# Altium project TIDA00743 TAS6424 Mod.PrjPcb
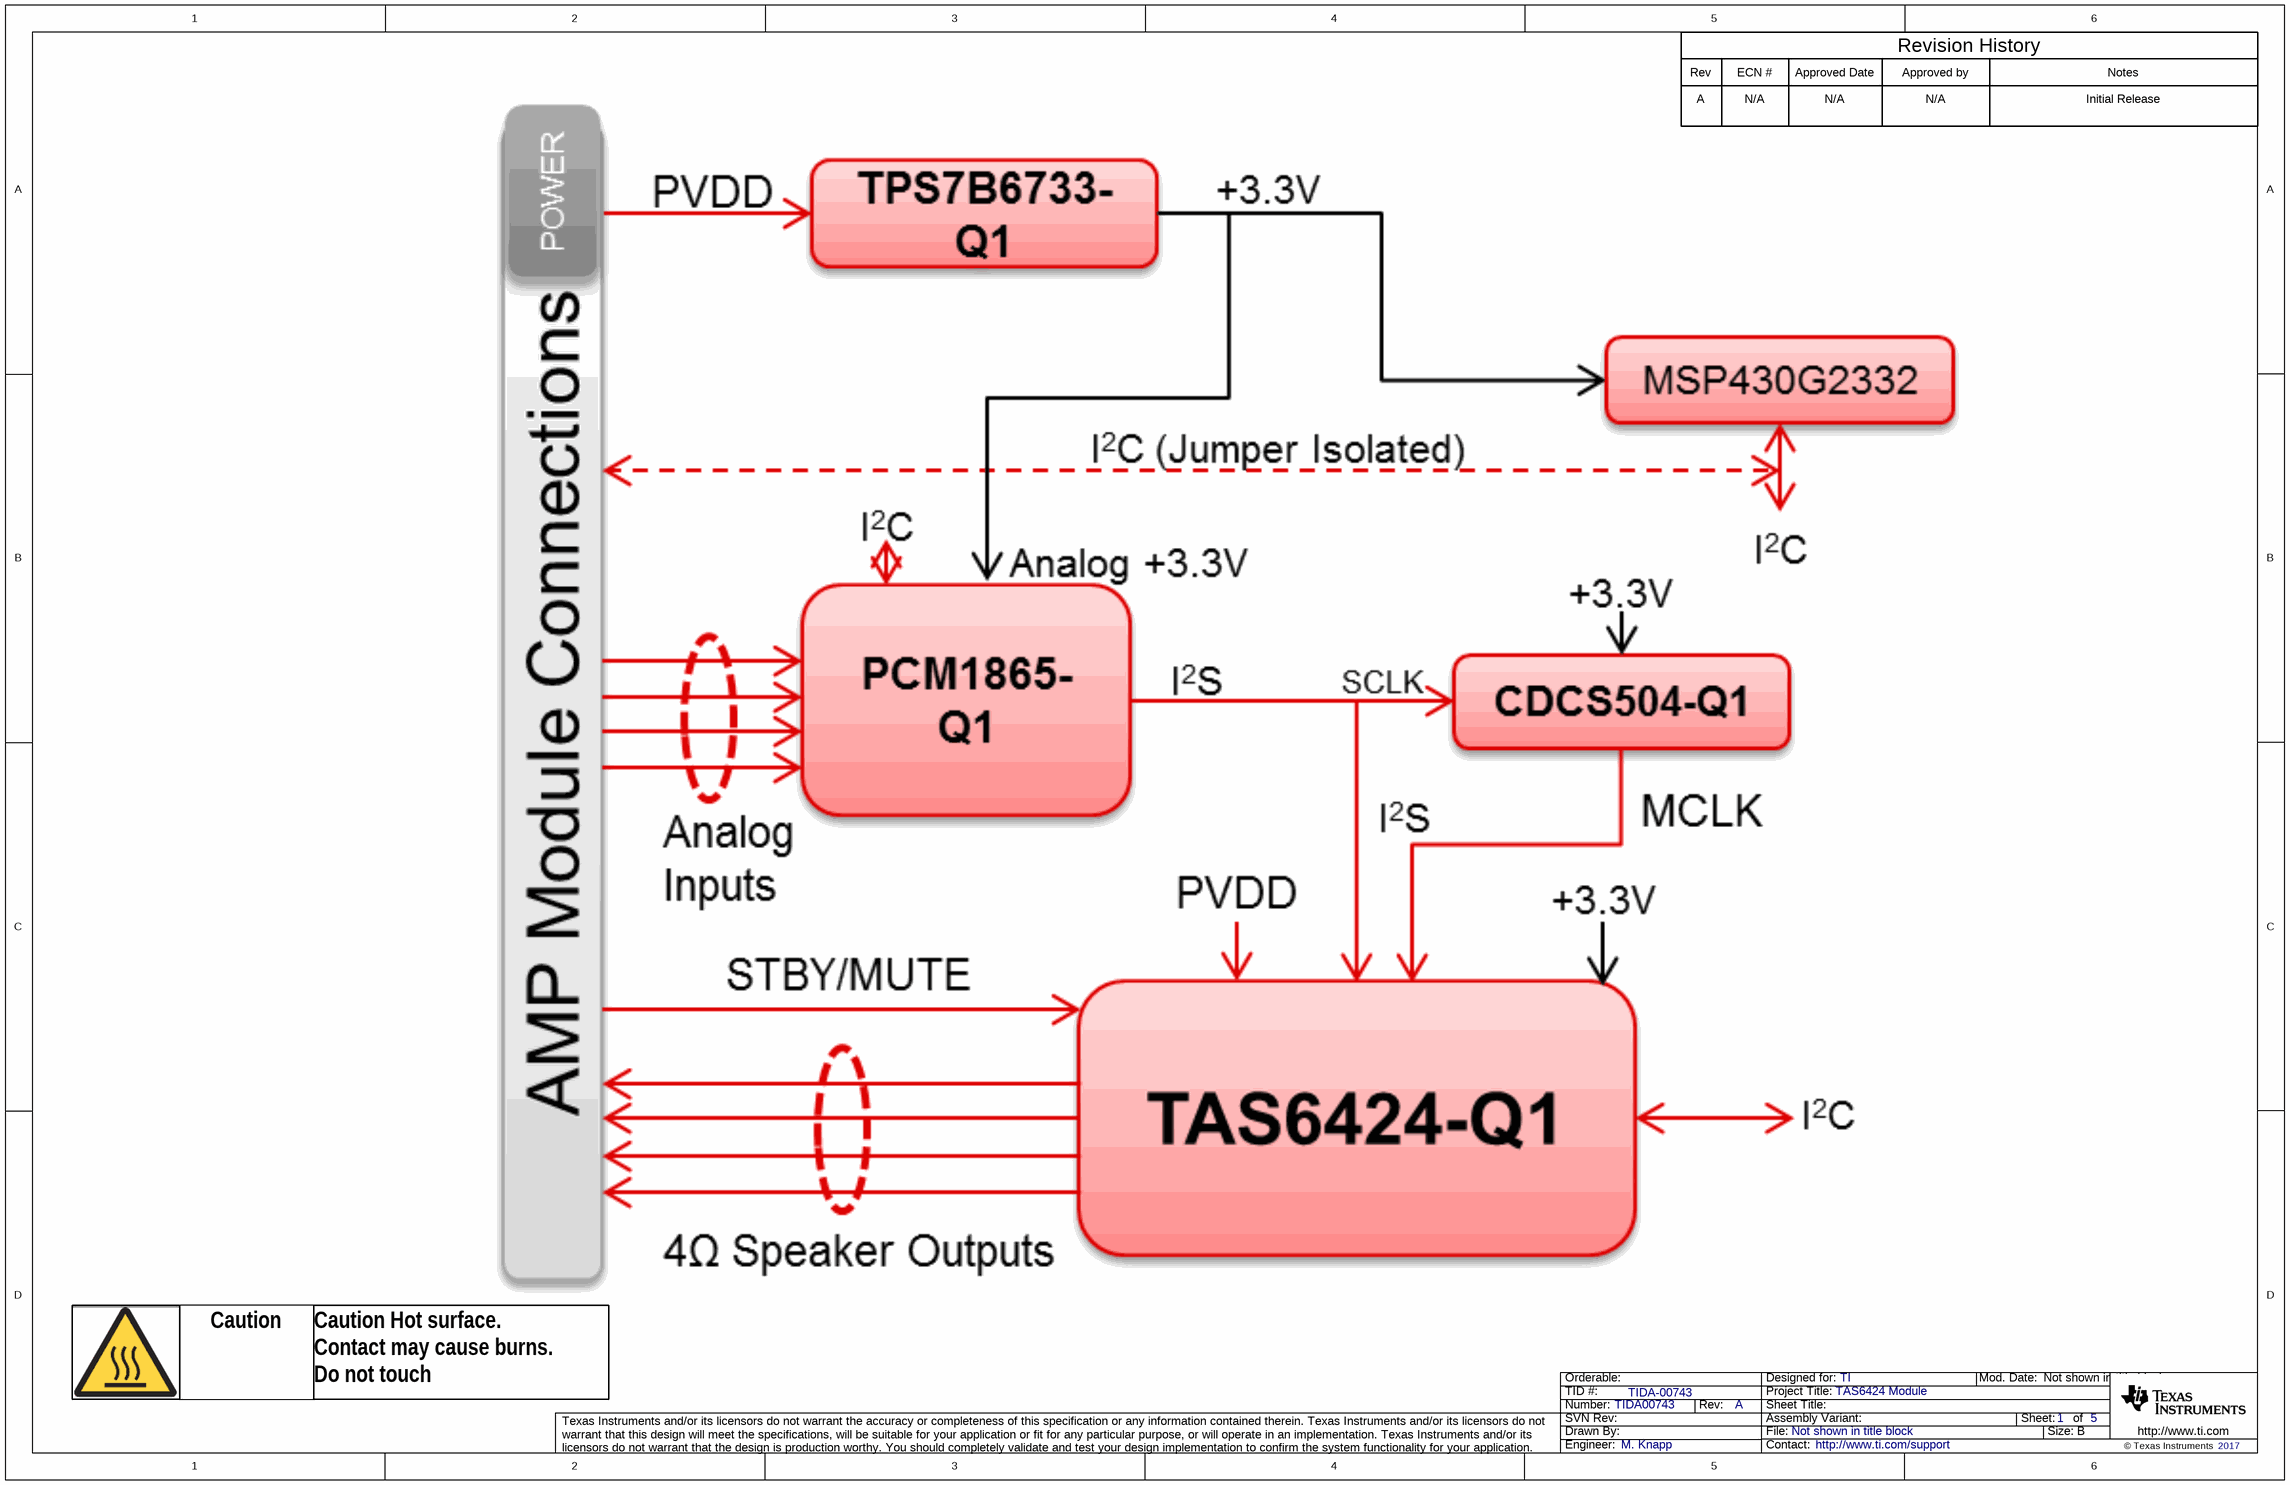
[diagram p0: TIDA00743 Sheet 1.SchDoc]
TID: TIDA-00743; TechSupport: http://www.ti.com/support; SCH_Rev: A; PRJ_Title: TAS6424 Module; PRJ_Number: TIDA00743; PRJ_Engineer: M. Knapp; PRJ_Customer: TI; PCB_Rev: A; PCB_Layout: M. Knapp; CopyrightYear: 2017
5 sheets, 145 parts. Net scope: global (net labels, ports and power ports of the same name join across sheets).
Board file: TIDA00743 PCB.PcbDoc
Sheets:
  TIDA00743 Sheet 1.SchDoc
  TIDA00743 Sheet 2.SchDoc
  TIDA00743 Sheet 3.SchDoc
  TIDA00743 Sheet 4.SchDoc
  TIDA00743 Sheet 5.SchDoc

## Sheet TIDA00743 Sheet 1.SchDoc
size 431 x 279 mm; Date: Not shown in title block; ApprovedBy: Not shown in title block; CheckedBy: Not shown in title block; Author: Not shown in title block; CompanyName: Not shown in title block; Engineer: Not shown in title block; Organization: Not shown in title block; Address1: Not shown in title block; Address2: Not shown in title block; Address3: Not shown in title block; Address4: Not shown in title block; DocumentNumber: 1; Revision: Use project parameter SCH_Rev; SheetNumber: 1; SheetTotal: 5; PageSetup: Record=PageOptions¦CenterHorizontal=True¦CenterVertical=True¦PrintScale=1.00¦XCorrection=1.00¦YCorrection=1.00¦PrintKind=0¦BorderSize=5000000¦LeftOffset=0¦BottomOffset=0¦Orientation=2¦PaperLength=1000¦PaperWidth=1000¦Scale=100¦PaperSource=15¦PrintQuality=600¦MediaType=1¦DitherType=10¦PaperKind=Letter¦PrintScaleMode=1

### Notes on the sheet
- Rev
- A
- ECN #
- N/A
- Approved Date
- Approved by
- Revision History
- Notes
- Initial Release
- Caution
- Caution Hot surface.
  Contact may cause burns.
  Do not touch

## Sheet TIDA00743 Sheet 2.SchDoc
size 431 x 279 mm; Date: Not shown in title block; ApprovedBy: Not shown in title block; CheckedBy: Not shown in title block; Author: Not shown in title block; CompanyName: Not shown in title block; Engineer: Not shown in title block; Organization: Not shown in title block; Address1: Not shown in title block; Address2: Not shown in title block; Address3: Not shown in title block; Address4: Not shown in title block; DocumentNumber: 2; Revision: Use project parameter SCH_Rev; SheetNumber: 2; SheetTotal: 5; PageSetup: Record=PageOptions¦CenterHorizontal=True¦CenterVertical=True¦PrintScale=1.00¦XCorrection=1.00¦YCorrection=1.00¦PrintKind=0¦BorderSize=5000000¦LeftOffset=0¦BottomOffset=0¦Orientation=2¦PaperLength=1000¦PaperWidth=1000¦Scale=100¦PaperSource=15¦PrintQuality=600¦MediaType=1¦DitherType=10¦PaperKind=Letter¦PrintScaleMode=1
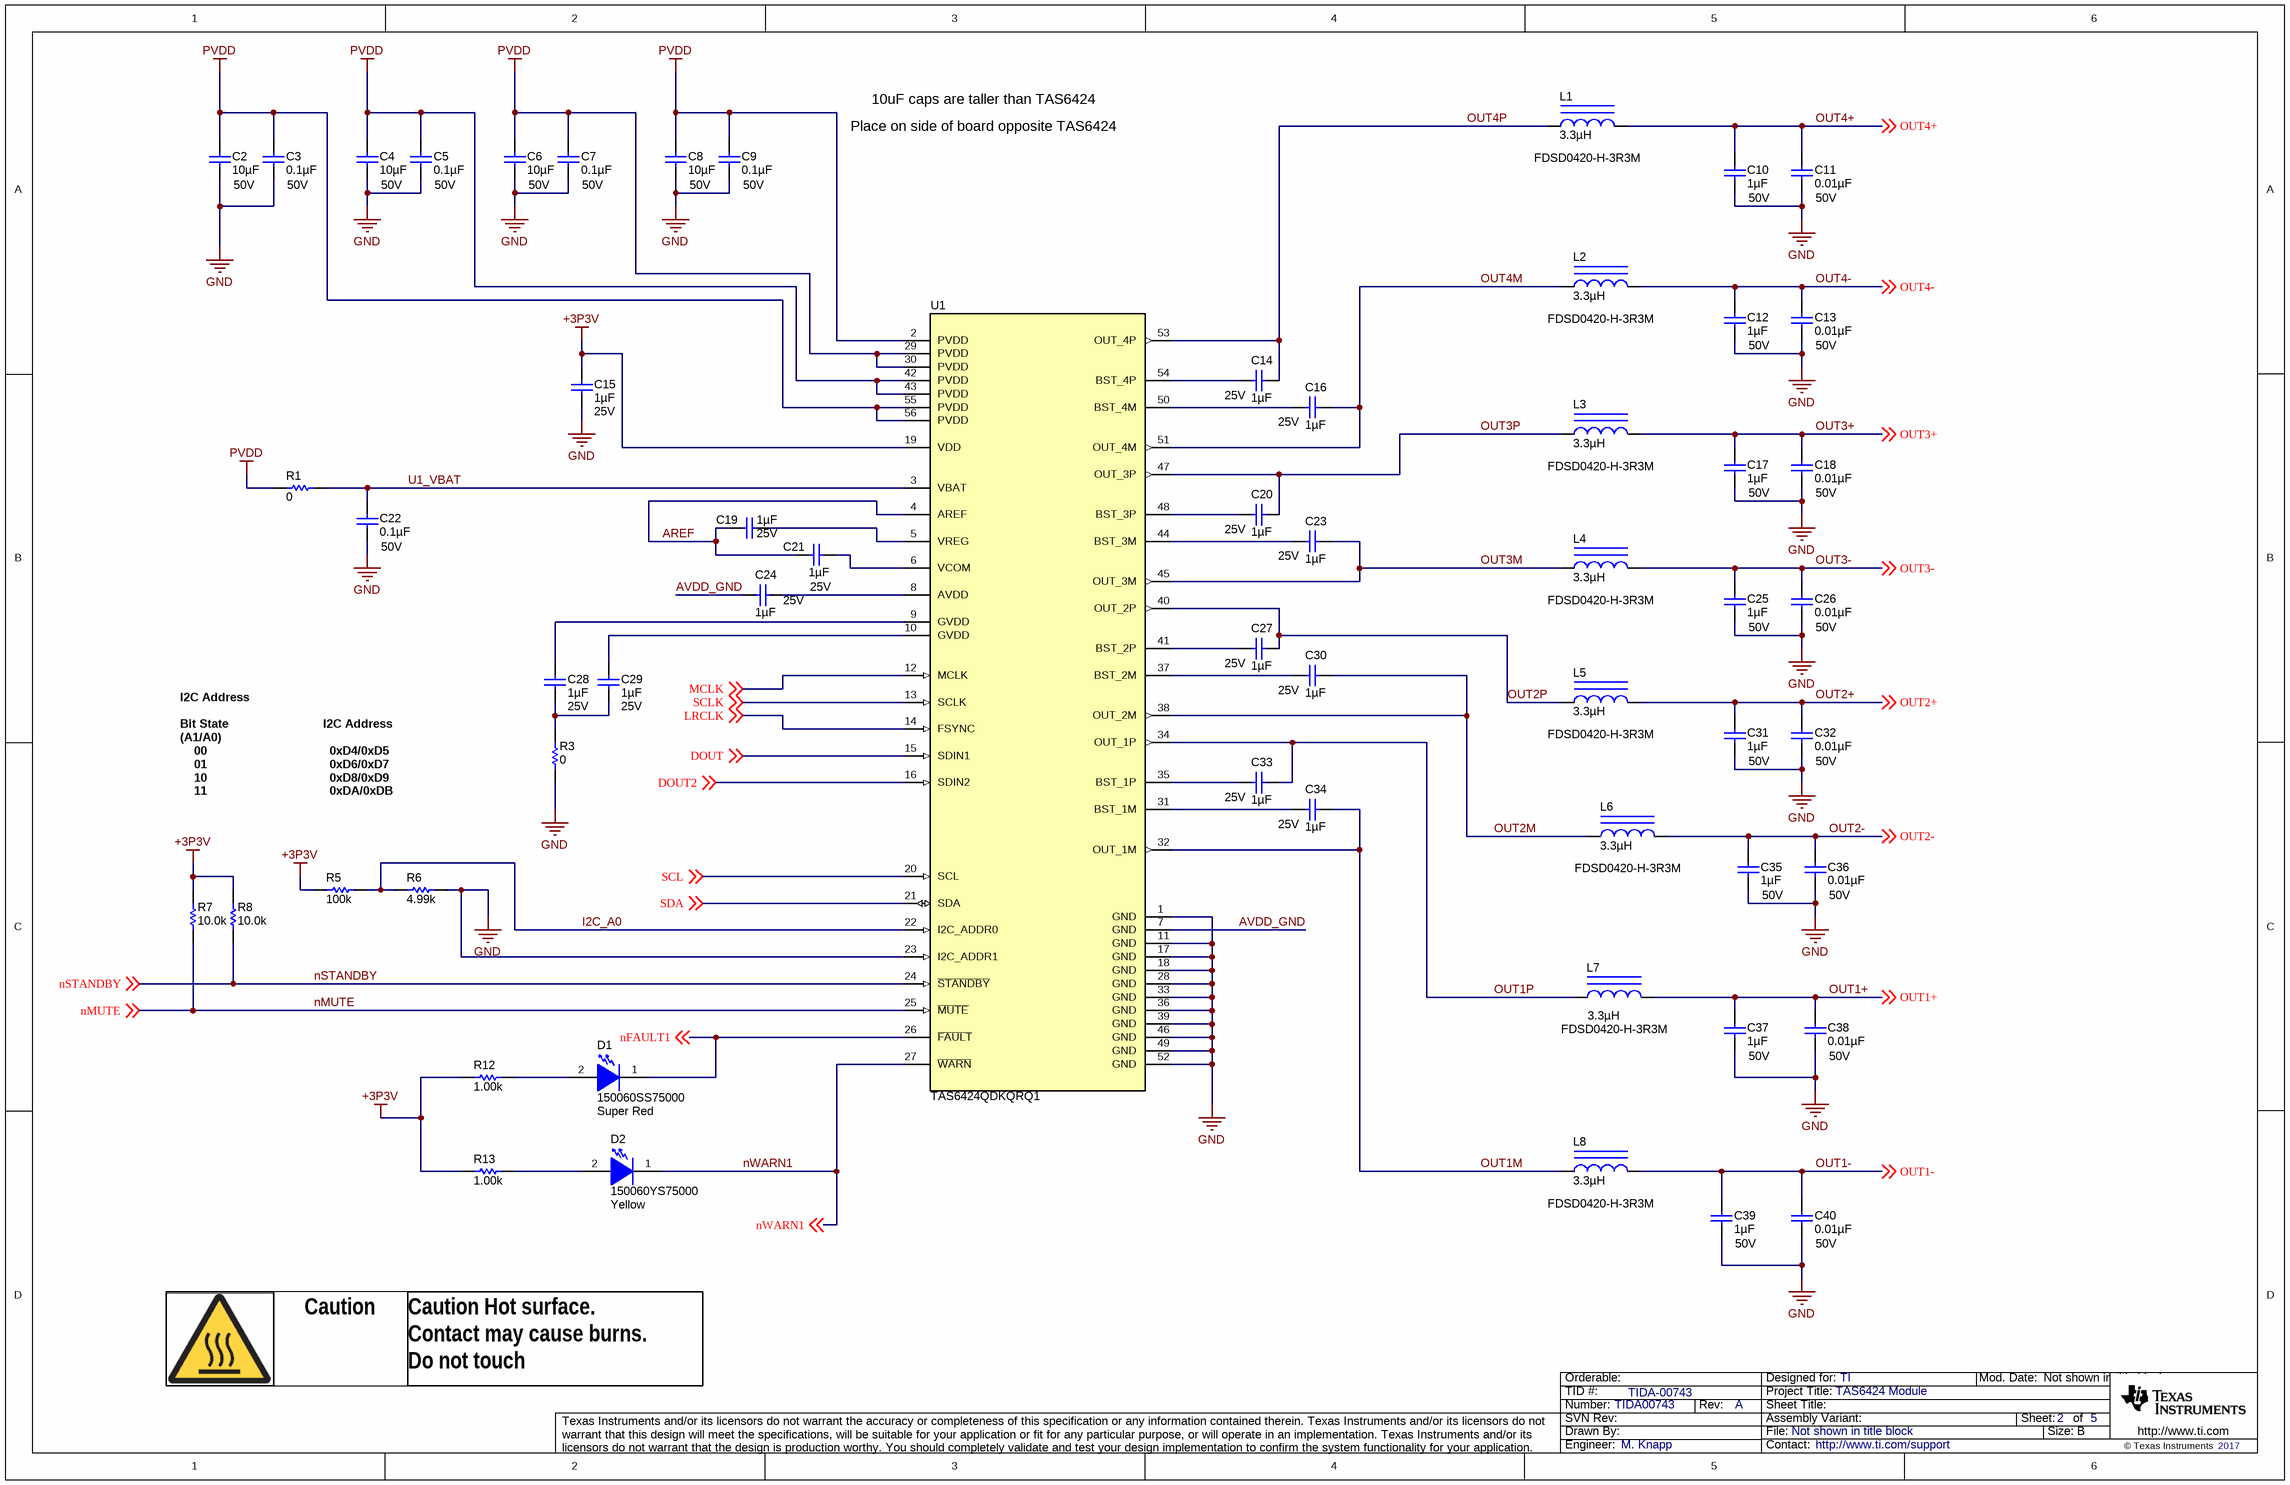
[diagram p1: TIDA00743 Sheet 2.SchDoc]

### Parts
C2  ValueDisplayed: 10µF  Value2: 50V  [1210L]  (hidden comment: GRM32ER71H106KA12L)
C3  ValueDisplayed: 0.1µF  Value2: 50V  [0402L]  (hidden comment: C1005X7R1H104K050BB)
C4  ValueDisplayed: 10µF  Value2: 50V  [1210L]  (hidden comment: GRM32ER71H106KA12L)
C5  ValueDisplayed: 0.1µF  Value2: 50V  [0402L]  (hidden comment: C1005X7R1H104K050BB)
C6  ValueDisplayed: 10µF  Value2: 50V  [1210L]  (hidden comment: GRM32ER71H106KA12L)
C7  ValueDisplayed: 0.1µF  Value2: 50V  [0402L]  (hidden comment: C1005X7R1H104K050BB)
C8  ValueDisplayed: 10µF  Value2: 50V  [1210L]  (hidden comment: GRM32ER71H106KA12L)
C9  ValueDisplayed: 0.1µF  Value2: 50V  [0402L]  (hidden comment: C1005X7R1H104K050BB)
C10  ValueDisplayed: 1µF  Value2: 50V  [0805L]  (hidden comment: GRM21BR71H105KA12L)
C11  ValueDisplayed: 0.01µF  Value2: 50V  [0402L]  (hidden comment: GCM155R71H103KA55D)
C12  ValueDisplayed: 1µF  Value2: 50V  [0805L]  (hidden comment: GRM21BR71H105KA12L)
C13  ValueDisplayed: 0.01µF  Value2: 50V  [0402L]  (hidden comment: GCM155R71H103KA55D)
C14  ValueDisplayed: 1µF  Value2: 25V  [0603L]  (hidden comment: C1608X7R1E105K080AB)
C15  ValueDisplayed: 1µF  Value2: 25V  [0603L]  (hidden comment: C1608X7R1E105K080AB)
C16  ValueDisplayed: 1µF  Value2: 25V  [0603L]  (hidden comment: C1608X7R1E105K080AB)
C17  ValueDisplayed: 1µF  Value2: 50V  [0805L]  (hidden comment: GRM21BR71H105KA12L)
C18  ValueDisplayed: 0.01µF  Value2: 50V  [0402L]  (hidden comment: GCM155R71H103KA55D)
C19  ValueDisplayed: 1µF  Value2: 25V  [0603L]  (hidden comment: C1608X7R1E105K080AB)
C20  ValueDisplayed: 1µF  Value2: 25V  [0603L]  (hidden comment: C1608X7R1E105K080AB)
C21  ValueDisplayed: 1µF  Value2: 25V  [0603L]  (hidden comment: C1608X7R1E105K080AB)
C22  ValueDisplayed: 0.1µF  Value2: 50V  [0402L]  (hidden comment: C1005X7R1H104K050BB)
C23  ValueDisplayed: 1µF  Value2: 25V  [0603L]  (hidden comment: C1608X7R1E105K080AB)
C24  ValueDisplayed: 1µF  Value2: 25V  [0603L]  (hidden comment: C1608X7R1E105K080AB)
C25  ValueDisplayed: 1µF  Value2: 50V  [0805L]  (hidden comment: GRM21BR71H105KA12L)
C26  ValueDisplayed: 0.01µF  Value2: 50V  [0402L]  (hidden comment: GCM155R71H103KA55D)
C27  ValueDisplayed: 1µF  Value2: 25V  [0603L]  (hidden comment: C1608X7R1E105K080AB)
C28  ValueDisplayed: 1µF  Value2: 25V  [0603L]  (hidden comment: C1608X7R1E105K080AB)
C29  ValueDisplayed: 1µF  Value2: 25V  [0603L]  (hidden comment: C1608X7R1E105K080AB)
C30  ValueDisplayed: 1µF  Value2: 25V  [0603L]  (hidden comment: C1608X7R1E105K080AB)
C31  ValueDisplayed: 1µF  Value2: 50V  [0805L]  (hidden comment: GRM21BR71H105KA12L)
C32  ValueDisplayed: 0.01µF  Value2: 50V  [0402L]  (hidden comment: GCM155R71H103KA55D)
C33  ValueDisplayed: 1µF  Value2: 25V  [0603L]  (hidden comment: C1608X7R1E105K080AB)
C34  ValueDisplayed: 1µF  Value2: 25V  [0603L]  (hidden comment: C1608X7R1E105K080AB)
C35  ValueDisplayed: 1µF  Value2: 50V  [0805L]  (hidden comment: GRM21BR71H105KA12L)
C36  ValueDisplayed: 0.01µF  Value2: 50V  [0402L]  (hidden comment: GCM155R71H103KA55D)
C37  ValueDisplayed: 1µF  Value2: 50V  [0805L]  (hidden comment: GRM21BR71H105KA12L)
C38  ValueDisplayed: 0.01µF  Value2: 50V  [0402L]  (hidden comment: GCM155R71H103KA55D)
C39  ValueDisplayed: 1µF  Value2: 50V  [0805L]  (hidden comment: GRM21BR71H105KA12L)
C40  ValueDisplayed: 0.01µF  Value2: 50V  [0402L]  (hidden comment: GCM155R71H103KA55D)
D1  value Super Red  [WL-SMCW_RED]  (hidden comment: 150060SS75000)
D2  value Yellow  [WL-SMCW_YELLOW]  (hidden comment: 150060YS75000)
L1  ValueDisplayed: 3.3µH  [FDSD0420]  (hidden comment: FDSD0420-H-3R3M)
L2  ValueDisplayed: 3.3µH  [FDSD0420]  (hidden comment: FDSD0420-H-3R3M)
L3  ValueDisplayed: 3.3µH  [FDSD0420]  (hidden comment: FDSD0420-H-3R3M)
L4  ValueDisplayed: 3.3µH  [FDSD0420]  (hidden comment: FDSD0420-H-3R3M)
L5  ValueDisplayed: 3.3µH  [FDSD0420]  (hidden comment: FDSD0420-H-3R3M)
L6  ValueDisplayed: 3.3µH  [FDSD0420]  (hidden comment: FDSD0420-H-3R3M)
L7  ValueDisplayed: 3.3µH  [FDSD0420]  (hidden comment: FDSD0420-H-3R3M)
L8  ValueDisplayed: 3.3µH  [FDSD0420]  (hidden comment: FDSD0420-H-3R3M)
R1  ValueDisplayed: 0  [0402L]  (hidden comment: CRCW04020000Z0ED)
R3  ValueDisplayed: 0  [0402L]  (hidden comment: CRCW04020000Z0ED)
R5  ValueDisplayed: 100k  [0402L]  (hidden comment: CRCW0402100KFKED)
R6  ValueDisplayed: 4.99k  [0402L]  (hidden comment: CRCW04024K99FKED)
R7  ValueDisplayed: 10.0k  [0402L]  (hidden comment: CRCW040210K0FKED)
R8  ValueDisplayed: 10.0k  [0402L]  (hidden comment: CRCW040210K0FKED)
R12  ValueDisplayed: 1.00k  [0402L]  (hidden comment: CRCW04021K00FKED)
R13  ValueDisplayed: 1.00k  [0402L]  (hidden comment: CRCW04021K00FKED)
U1  TAS6424QDKQRQ1  [DKQ0056A]

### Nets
+3P3V: C15.1 R5.1 R7.2 R8.2 R12.1 R13.1 U1.19(VDD)
GND: C2.2 C3.2 C4.2 C5.2 C6.2 C7.2 C8.2 C9.2 C10.2 C11.2 C12.2 C13.2 C15.2 C17.2 C18.2 C22.2 C25.2 C26.2 C31.2 C32.2 C35.2 C36.2 C37.2 C38.2 C39.2 C40.2 R3.1 R6.2 U1.1(GND) U1.11(GND) U1.17(GND) U1.18(GND) U1.23(I2C_ADDR1) U1.28(GND) U1.33(GND) U1.36(GND) U1.39(GND) U1.46(GND) U1.49(GND) U1.52(GND)
PVDD: C2.1 C3.1 C4.1 C5.1 C6.1 C7.1 C8.1 C9.1 R1.1 U1.2(PVDD) U1.29(PVDD) U1.30(PVDD) U1.42(PVDD) U1.43(PVDD) U1.55(PVDD) U1.56(PVDD)
AREF: C19.2 C21.2 U1.4(AREF)
AVDD_GND: C24.2 U1.7(GND)
DOUT: U1.15(SDIN1) ; off-sheet DOUT
DOUT2: U1.16(SDIN2) ; off-sheet DOUT2
I2C_A0: R5.2 R6.1 U1.22(I2C_ADDR0)
LRCLK: U1.14(FSYNC) ; off-sheet LRCLK
MCLK: U1.12(MCLK) ; off-sheet MCLK
nFAULT1: D1.1(K) U1.26(~{FAULT}) ; off-sheet nFAULT1
nMUTE: R7.1 U1.25(~{MUTE}) ; off-sheet nMUTE
nSTANDBY: R8.1 U1.24(~{STANDBY}) ; off-sheet nSTANDBY
nWARN1: D2.1(K) U1.27(~{WARN}) ; off-sheet nWARN1
OUT1+: C37.1 C38.1 L7.2 ; off-sheet OUT1+
OUT1-: C39.1 C40.1 L8.2 ; off-sheet OUT1-
OUT1M: C34.1 L8.1 U1.32(OUT_1M)
OUT1P: C33.1 L7.1 U1.34(OUT_1P)
OUT2+: C31.1 C32.1 L5.2 ; off-sheet OUT2+
OUT2-: C35.1 C36.1 L6.2 ; off-sheet OUT2-
OUT2M: C30.1 L6.1 U1.38(OUT_2M)
OUT2P: C27.1 L5.1 U1.40(OUT_2P)
OUT3+: C17.1 C18.1 L3.2 ; off-sheet OUT3+
OUT3-: C25.1 C26.1 L4.2 ; off-sheet OUT3-
OUT3M: C23.1 L4.1 U1.45(OUT_3M)
OUT3P: C20.1 L3.1 U1.47(OUT_3P)
OUT4+: C10.1 C11.1 L1.2 ; off-sheet OUT4+
OUT4-: C12.1 C13.1 L2.2 ; off-sheet OUT4-
OUT4M: C16.1 L2.1 U1.51(OUT_4M)
OUT4P: C14.1 L1.1 U1.53(OUT_4P)
SCL: U1.20(SCL) ; off-sheet SCL
SCLK: U1.13(SCLK) ; off-sheet SCLK
SDA: U1.21(SDA) ; off-sheet SDA
U1_VBAT: C22.1 R1.2 U1.3(VBAT)
NetC14_2: C14.2 U1.54(BST_4P)
NetC16_2: C16.2 U1.50(BST_4M)
NetC19_1: C19.1 U1.5(VREG)
NetC20_2: C20.2 U1.48(BST_3P)
NetC21_1: C21.1 U1.6(VCOM)
NetC23_2: C23.2 U1.44(BST_3M)
NetC24_1: C24.1 U1.8(AVDD)
NetC27_2: C27.2 U1.41(BST_2P)
NetC28_1: C28.1 U1.9(GVDD)
NetC28_2: C28.2 C29.2 R3.2
NetC29_1: C29.1 U1.10(GVDD)
NetC30_2: C30.2 U1.37(BST_2M)
NetC33_2: C33.2 U1.35(BST_1P)
NetC34_2: C34.2 U1.31(BST_1M)
NetD1_2: D1.2(A) R12.2
NetD2_2: D2.2(A) R13.2

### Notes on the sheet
- 10uF caps are taller than TAS6424
- Place on side of board opposite TAS6424
- I2C Address
  Bit State                           I2C Address
  (A1/A0)
  00                                   0xD4/0xD5
  01                                   0xD6/0xD7
  10                                   0xD8/0xD9
  11                                   0xDA/0xDB
- Caution
- Caution Hot surface.
  Contact may cause burns.
  Do not touch

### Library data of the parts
C2 C4 C6 C8 = GRM32ER71H106KA12L: CAP, CERM, 10 µF, 50 V, +/- 10%, X7R, 1210; Manufacturer: MuRata; Polarized: N; CompType: Capacitor; Value: 10uF; U/M: EA; Cap_F: 0.00001; Tolerance_%: 10; Value1: Unknown; VDC_V: 50; TaMin_C: -55; TaMax_C: 125; Cap_Case: 1210; AEC Category: Q200
C3 C5 C7 C9 C22 = C1005X7R1H104K050BB: CAP, CERM, 0.1 µF, 50 V, +/- 10%, X7R, 0402; Manufacturer: TDK; Polarized: N; CompType: Capacitor; Value: 0.1uF; U/M: EA; Cap_F: 0.0000001; Tolerance_%: 10; Value1: Unknown; VDC_V: 50; TaMin_C: -55; TaMax_C: 125; Cap_Case: 0402; AEC Category: Q200
C10 C12 C17 C25 C31 C35 C37 C39 = GRM21BR71H105KA12L: CAP, CERM, 1 µF, 50 V, +/- 10%, X7R, 0805; Manufacturer: MuRata; Polarized: N; CompType: Capacitor; Value: 1uF; U/M: EA; Cap_F: 0.000001; Tolerance_%: 10; Value1: Unknown; VDC_V: 50; TaMin_C: -55; TaMax_C: 125; Cap_Case: 0805; AEC Category: Q200
C11 C13 C18 C26 C32 C36 C38 C40 = GCM155R71H103KA55D: CAP, CERM, 0.01 µF, 50 V, +/- 10%, C0G/NP0, 0402; Manufacturer: MuRata; Polarized: N; CompType: Capacitor; Value: 0.01uF; U/M: EA; Cap_F: 0.00000001; Tolerance_%: 10; Value1: Unknown; VDC_V: 50; TaMin_C: -55; TaMax_C: 125; Cap_Case: 0402; AEC Category: Q200
C14 C16 C20 C23 C27 C30 C33 C34 = C1608X7R1E105K080AB: CAP, CERM, 1 µF, 25 V, +/- 10%, X7R, 0603; Manufacturer: TDK; Polarized: N; CompType: Capacitor; Value: 1uF; U/M: EA; Cap_F: 0.000001; Tolerance_%: 10; Value1: Unknown; VDC_V: 25; TaMin_C: -55; TaMax_C: 125; Cap_Case: 0603; AEC Category: Q200; SizeArea_mm2: 1.28; SizeAreaWB_mm2: 4.68; SizeX_mm: 1.6; SizeY_mm: 0.8; SizeZ_mm: 1
C15 C19 C21 C24 C28 C29 = C1608X7R1E105K080AB: CAP, CERM, 1 µF, 25 V, +/- 10%, X7R, 0603; Manufacturer: TDK; Polarized: N; CompType: Capacitor; Value: 1uF; U/M: EA; Cap_F: 0.000001; Tolerance_%: 10; Value1: Unknown; VDC_V: 25; TaMin_C: -55; TaMax_C: 125; Cap_Case: 0603; AEC Category: Q200
D1 = 150060SS75000: LED, Super Red, SMD; Manufacturer: Wurth Elektronik; Type: AlInGaP; Vf_V: 1.9; Value2: 1.9V; Io_A: 0.02; Value1: W; U/M: EA
D2 = 150060YS75000: LED, Yellow, SMD; Manufacturer: Wurth Elektronik; Type: AlInGaP; Vf_V: 2; Value2: 2V; Io_A: 0.02; Value1: W; U/M: EA
L1-L8 = FDSD0420-H-3R3M: Inductor, Shielded, Powdered Iron, 3.3 µH, 3.4 A, 0.059 ohm, SMD; Manufacturer: Toko; Value: 3.3uH; Ind_H: 3.3E-6; Imax_A: 3.4; Irms: 3.4A @ 40C rise; Isat: 4.9A @ 30% inductance drop; DCR_ohm: 0.059; Value2: 3.4A; AEC Category: Q200
R1 = CRCW04020000Z0ED: RES, 0, 5%, 0.063 W, 0402; Manufacturer: Vishay-Dale; CompType: Resistor; Value: 0; Value_Code: 0000; Tolerance_%: 5; Power_W: 0.063; Value2: 0.063W; VDC_V: 50; TempCo: 200 ppm/C; EIA_Code: E24; U/M: EA; AEC Category: Q200; SizeArea_mm2: 0.5; SizeX_mm: 1; SizeZ_mm: 0.6
R3 = CRCW04020000Z0ED: RES, 0, 5%, 0.063 W, 0402; Manufacturer: Vishay-Dale; CompType: Resistor; Value: 0; Value_Code: 0000; Tolerance_%: 5; Power_W: 0.063; Value2: 0.063W; VDC_V: 50; TempCo: 200 ppm/C; EIA_Code: E24; U/M: EA; AEC Category: Q200
R5 = CRCW0402100KFKED: RES, 100 k, 1%, 0.063 W, 0402; Manufacturer: Vishay-Dale; CompType: Resistor; Value: 100k; Res_ohm: 100000; Tolerance_%: 1; Power_W: 0.063; Value2: 0.063W; VDC_V: 50; TempCo: 100 ppm/C; EIA_Code: E96; U/M: EA; AEC Category: Q200
R6 = CRCW04024K99FKED: RES, 4.99 k, 1%, 0.063 W, 0402; Manufacturer: Vishay-Dale; CompType: Resistor; Value: 4.99k; Res_ohm: 4990; Value_Code: 4k99; Tolerance_%: 1; Power_W: 0.063; Value2: 0.063W; VDC_V: 50; TempCo: 100 ppm/C; EIA_Code: E96; U/M: EA; AEC Category: Q200
R7 R8 = CRCW040210K0FKED: RES, 10.0 k, 1%, 0.063 W, 0402; Manufacturer: Vishay-Dale; CompType: Resistor; Value: 10.0k; Res_ohm: 10000; Value_Code: 10k0; Tolerance_%: 1; Power_W: 0.063; Value2: 0.063W; VDC_V: 50; TempCo: 100 ppm/C; EIA_Code: E96; U/M: EA; AEC Category: Q200
R12 R13 = CRCW04021K00FKED: RES, 1.00 k, 1%, 0.063 W, 0402; Manufacturer: Vishay-Dale; CompType: Resistor; Value: 1.00k; Res_ohm: 1000; Value_Code: 1k00; Tolerance_%: 1; Power_W: 0.063; Value2: 0.063W; VDC_V: 50; TempCo: 100 ppm/C; EIA_Code: E96; U/M: EA; AEC Category: Q200
U1 = TAS6424QDKQRQ1: Four-Channel Digital Input Automotive Digital Amplifier, DKQ0056A; Manufacturer: Texas Instruments; SymbolCreator: Altium; CompType: IC; U/M: EA; SizeArea_mm2: 190.5435; SizeAreaWB_mm2: 252.0635; SizeX_mm: 10.35; SizeY_mm: 18.41; SizeZ_mm: 2.79

## Sheet TIDA00743 Sheet 3.SchDoc
size 431 x 279 mm; Date: Not shown in title block; ApprovedBy: Not shown in title block; CheckedBy: Not shown in title block; Author: Not shown in title block; CompanyName: Not shown in title block; Engineer: Not shown in title block; Organization: Not shown in title block; Address1: Not shown in title block; Address2: Not shown in title block; Address3: Not shown in title block; Address4: Not shown in title block; DocumentNumber: 3; Revision: Use project parameter SCH_Rev; SheetNumber: 3; SheetTotal: 5; PageSetup: Record=PageOptions¦CenterHorizontal=True¦CenterVertical=True¦PrintScale=1.00¦XCorrection=1.00¦YCorrection=1.00¦PrintKind=0¦BorderSize=5000000¦LeftOffset=0¦BottomOffset=0¦Orientation=2¦PaperLength=1000¦PaperWidth=1000¦Scale=100¦PaperSource=15¦PrintQuality=600¦MediaType=1¦DitherType=10¦PaperKind=Letter¦PrintScaleMode=1
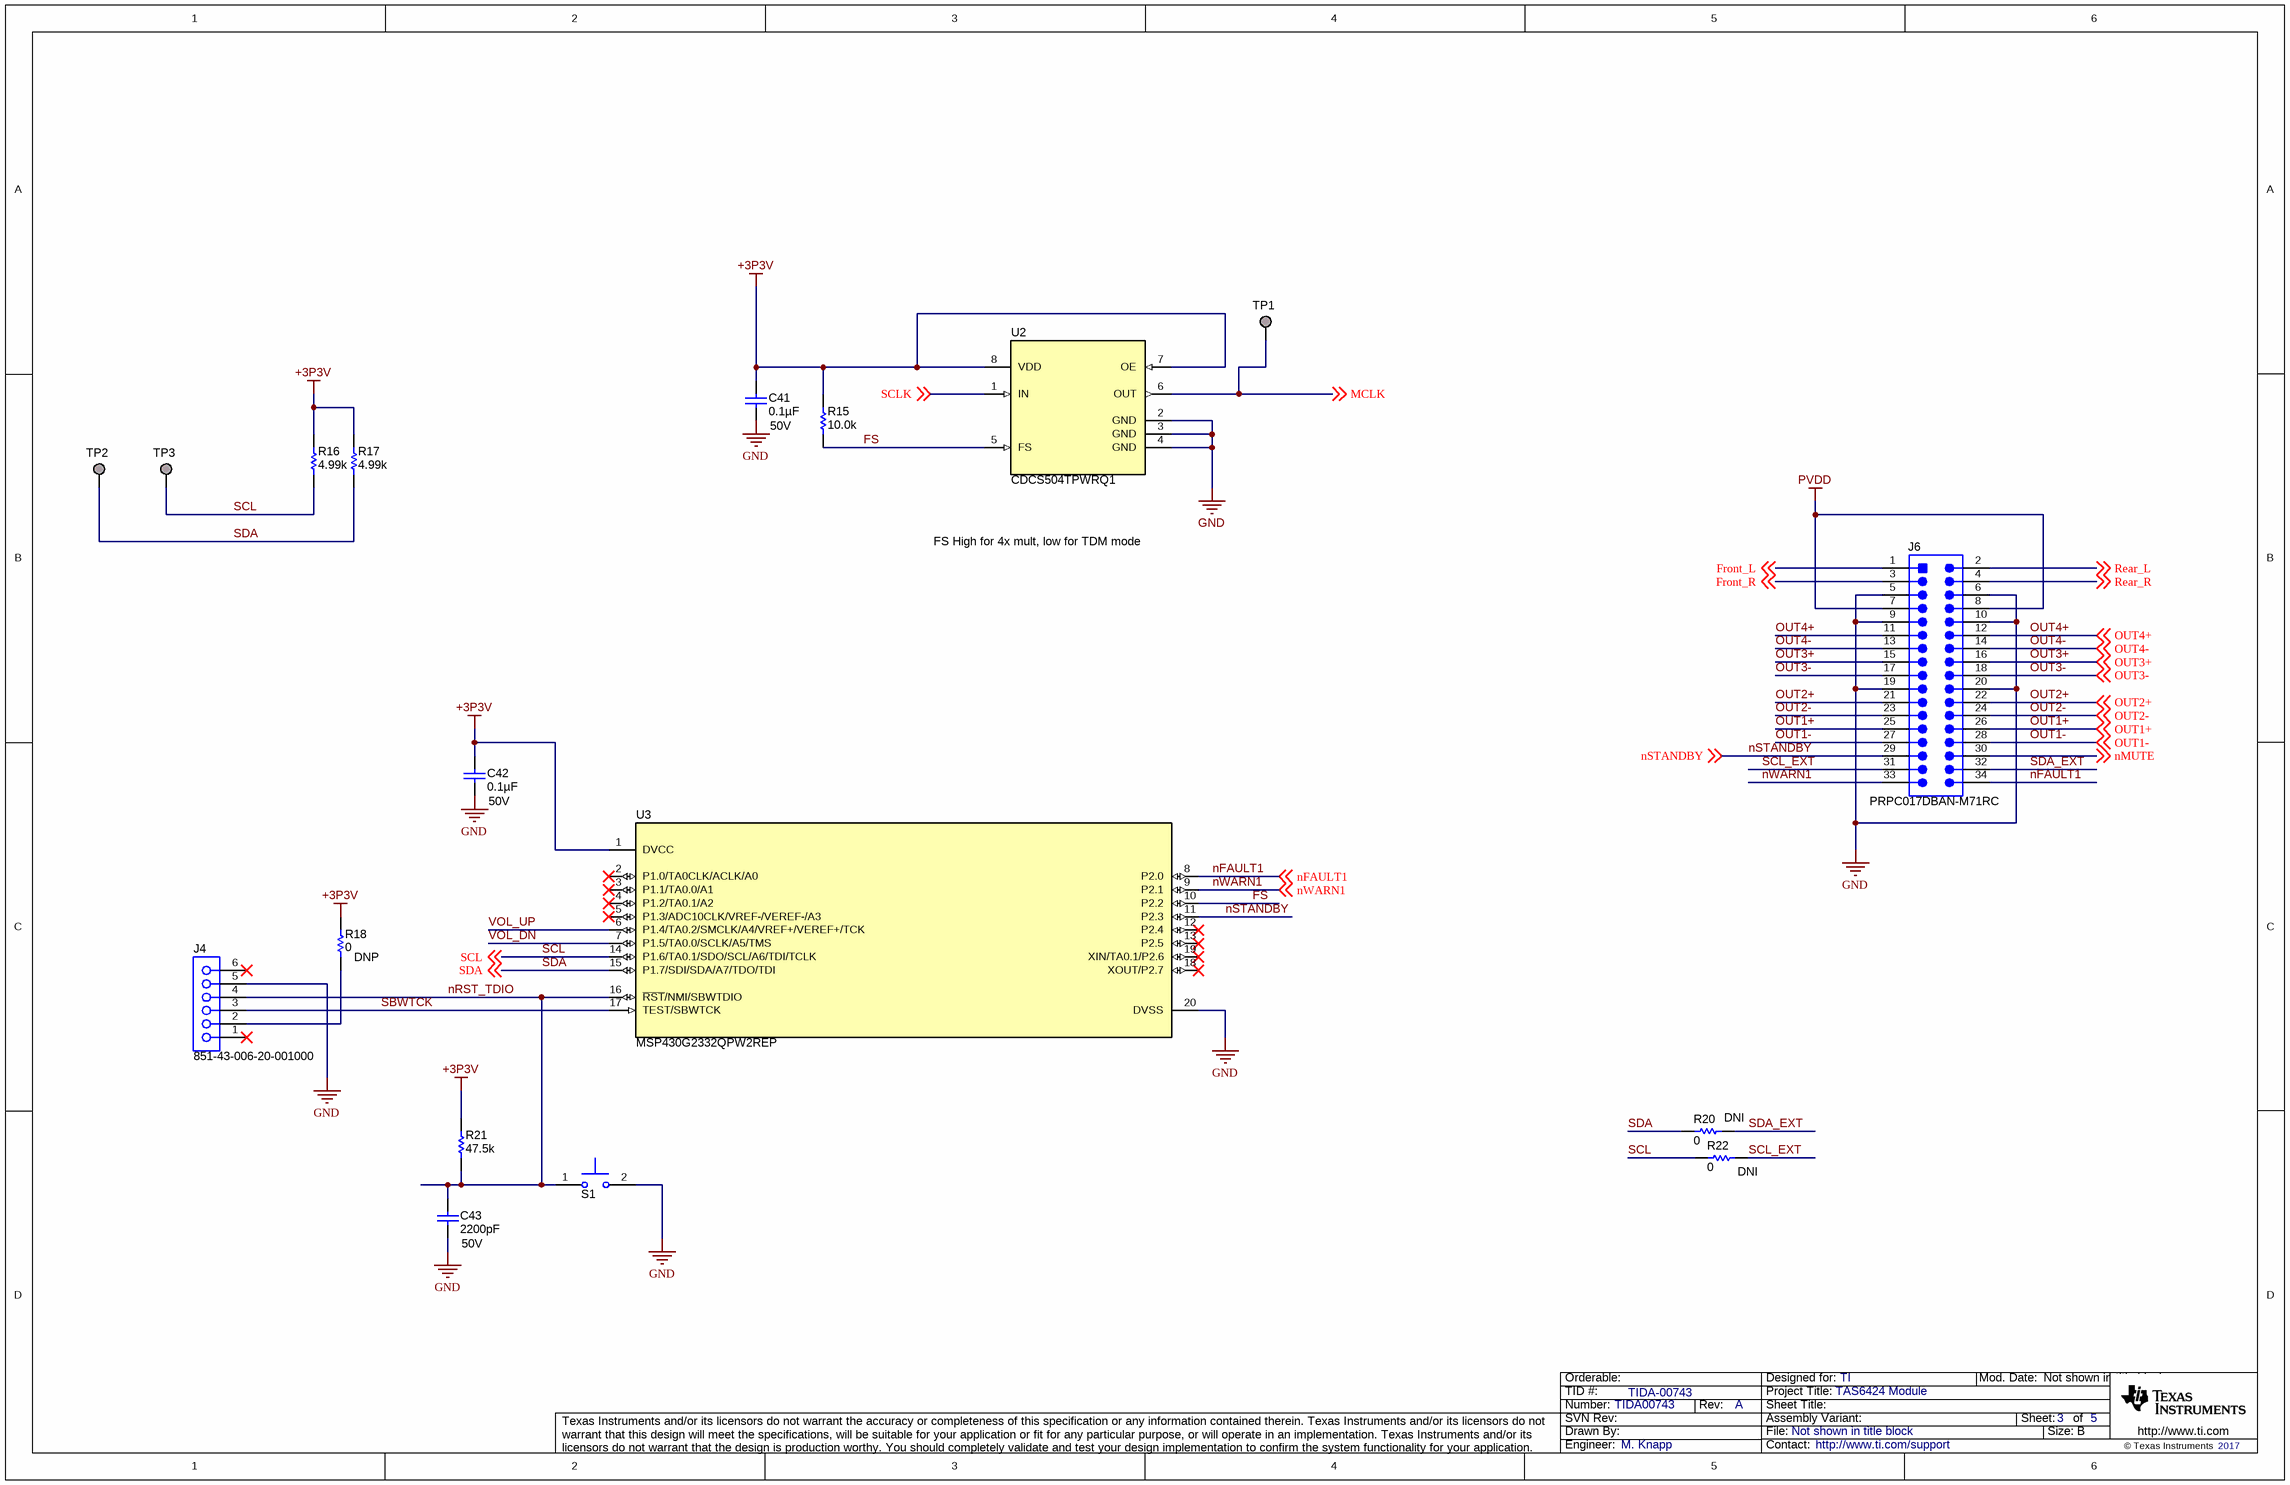
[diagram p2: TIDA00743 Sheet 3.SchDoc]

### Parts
C41  ValueDisplayed: 0.1µF  Value2: 50V  [0402L]  (hidden comment: C1005X7R1H104K050BB)
C42  ValueDisplayed: 0.1µF  Value2: 50V  [0402L]  (hidden comment: C1005X7R1H104K050BB)
C43  ValueDisplayed: 2200pF  Value2: 50V  [0402L]  (hidden comment: C1005X7R1H222K)
J4  851-43-006-20-001000  [CONN_851-43-006-20-001000]
J6  PRPC017DBAN-M71RC  [Sullins_PRxC017DBAN-M71RC]
R15  ValueDisplayed: 10.0k  [0402L]  (hidden comment: CRCW040210K0FKED)
R16  ValueDisplayed: 4.99k  [0402L]  (hidden comment: CRCW04024K99FKED)
R17  ValueDisplayed: 4.99k  [0402L]  (hidden comment: CRCW04024K99FKED)
R18  ValueDisplayed: 0  [0402L]  (hidden comment: CRCW04020000Z0ED)
R20  ValueDisplayed: 0  [0402L]  (hidden comment: CRCW04020000Z0ED)
R21  ValueDisplayed: 47.5k  [0402L]  (hidden comment: CRCW040247K5FKED)
R22  ValueDisplayed: 0  [0402L]  (hidden comment: CRCW04020000Z0ED)
S1  SKRKAEE010  [SW_SKRKAEE010]  (value not drawn)
TP1  TESTPOINT  [PAD_1MM_SQUARE]  (value not drawn)  (no BOM)
TP2  TESTPOINT  [PAD_1MM_SQUARE]  (value not drawn)  (no BOM)
TP3  TESTPOINT  [PAD_1MM_SQUARE]  (value not drawn)  (no BOM)
U2  CDCS504TPWRQ1  [PW0008A_N]
U3  MSP430G2332QPW2REP  [PW0020A_N]

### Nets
+3P3V: C41.1 C42.1 R15.2 R16.2 R17.2 R18.2 R21.2 U2.7(OE) U2.8(VDD) U3.1(DVCC)
GND: C41.2 C42.2 C43.2 J4.5 J6.5 J6.6 J6.9 J6.10 J6.19 J6.20 S1.2 U2.2(GND) U2.3(GND) U2.4(GND) U3.20(DVSS)
PVDD: J6.7 J6.8
Front_L: J6.1 ; off-sheet Front_L
Front_R: J6.3 ; off-sheet Front_R
FS: R15.1 U2.5(FS) U3.10(P2.2)
MCLK: TP1.1 U2.6(OUT) ; off-sheet MCLK
nFAULT1: J6.34 U3.8(P2.0) ; off-sheet nFAULT1
nMUTE: J6.30 ; off-sheet nMUTE
nRST_TDIO: C43.1 J4.4 R21.1 S1.1 U3.16(~{RST}/NMI/SBWTDIO)
nSTANDBY: J6.29 U3.11(P2.3) ; off-sheet nSTANDBY
nWARN1: J6.33 U3.9(P2.1) ; off-sheet nWARN1
OUT1+: J6.25 J6.26 ; off-sheet OUT1+
OUT1-: J6.27 J6.28 ; off-sheet OUT1-
OUT2+: J6.21 J6.22 ; off-sheet OUT2+
OUT2-: J6.23 J6.24 ; off-sheet OUT2-
OUT3+: J6.15 J6.16 ; off-sheet OUT3+
OUT3-: J6.17 J6.18 ; off-sheet OUT3-
OUT4+: J6.11 J6.12 ; off-sheet OUT4+
OUT4-: J6.13 J6.14 ; off-sheet OUT4-
Rear_L: J6.2 ; off-sheet Rear_L
Rear_R: J6.4 ; off-sheet Rear_R
SBWTCK: J4.3 U3.17(TEST/SBWTCK)
SCL: R16.1 R22.2 TP3.1 U3.14(P1.6/TA0.1/SDO/SCL/A6/TDI/TCLK) ; off-sheet SCL
SCL_EXT: J6.31 R22.1
SCLK: U2.1(IN) ; off-sheet SCLK
SDA: R17.1 R20.2 TP2.1 U3.15(P1.7/SDI/SDA/A7/TDO/TDI) ; off-sheet SDA
SDA_EXT: J6.32 R20.1
VOL_DN: U3.7(P1.5/TA0.0/SCLK/A5/TMS)
VOL_UP: U3.6(P1.4/TA0.2/SMCLK/A4/VREF+/VEREF+/TCK)
NetJ4_2: J4.2 R18.1

Not connected (* = marked no-connect by the designer): J4 1* 6*; U3 2(P1.0/TA0CLK/ACLK/A0)* 3(P1.1/TA0.0/A1)* 4(P1.2/TA0.1/A2)* 5(P1.3/ADC10CLK/VREF-/VEREF-/A3)* 12(P2.4)* 13(P2.5)* 18(XOUT/P2.7)* 19(XIN/TA0.1/P2.6)*

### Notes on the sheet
- FS High for 4x mult, low for TDM mode
- (near R18) DNP
- (near R20) DNI
- (near R22) DNI

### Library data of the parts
C41 C42 = C1005X7R1H104K050BB: as C3 on sheet TIDA00743 Sheet 2
C43 = C1005X7R1H222K: CAP, CERM, 2200 pF, 50 V, +/- 10%, X7R, 0402; Manufacturer: TDK; Polarized: N; CompType: Capacitor; Value: 2200pF; U/M: EA; Cap_F: 0.0000000022; Tolerance_%: 10; ESR_ohm: 0.1433; Value1: 0.1433 ohm; VDC_V: 50; TaMin_C: -55; TaMax_C: 125; Cap_Case: 0402; AEC Category: Q200
J4 = 851-43-006-20-001000: Receptacle, 50mil, 6x1, R/A, TH; Manufacturer: Mill-Max; SymbolCreator: a0411947; U/M: EA
J6 = PRPC017DBAN-M71RC: Header, 2.54mm, 17x2, Gold, R/A, TH; Manufacturer: Sullins Connector Solutions; SymbolCreator: a0411947; Pitch_mm: 2.54; Gender: Male; Shrouded: N; Row_Count: 2; Current_A: 3; Voltage_V: 1000; Cert_UL: Y
R15 = CRCW040210K0FKED: as R7 on sheet TIDA00743 Sheet 2
R16 R17 = CRCW04024K99FKED: as R6 on sheet TIDA00743 Sheet 2
R18 R20 R22 = CRCW04020000Z0ED: as R3 on sheet TIDA00743 Sheet 2
R21 = CRCW040247K5FKED: RES, 47.5 k, 1%, 0.063 W, 0402; Manufacturer: Vishay-Dale; CompType: Resistor; Value: 47.5k; Res_ohm: 47500; Value_Code: 47k5; Tolerance_%: 1; Power_W: 0.063; Value2: 0.063W; VDC_V: 50; TempCo: 100 ppm/C; EIA_Code: E96; U/M: EA; AEC Category: Q200
S1 = SKRKAEE010: Switch, Push Button, SMD; Manufacturer: Alps; SymbolCreator: a0412235; Circuit: SPST-NO; VDC_V: 12; SwitchFunction: Off-Mom; PositionCount: 1; CurrentRating_mA: 50
TP1-TP3 = PAD_1MM_SQUARE: 1.0x1.0mm pad, square, SMD; Manufacturer: Any
U2 = CDCS504TPWRQ1: Clock Buffer/Clock Multiplier, PW0008A (TSSOP-8); Manufacturer: Texas Instruments; SymbolCreator: a0411947; CompType: IC; U/M: EA; SizeArea_mm2: 19.2; SizeAreaWB_mm2: 42; SizeX_mm: 6.4; SizeY_mm: 3; SizeZ_mm: 1.2
U3 = MSP430G2332QPW2REP: MIXED SIGNAL MICROCONTROLLER, PW0020A; Alternate PartNumber: MSP430G2332QPW2EP; Manufacturer: Texas Instruments; SymbolCreator: Altium; CompType: IC; U/M: EA

## Sheet TIDA00743 Sheet 4.SchDoc
size 431 x 279 mm; Date: Not shown in title block; ApprovedBy: Not shown in title block; CheckedBy: Not shown in title block; Author: Not shown in title block; CompanyName: Not shown in title block; Engineer: Not shown in title block; Organization: Not shown in title block; Address1: Not shown in title block; Address2: Not shown in title block; Address3: Not shown in title block; Address4: Not shown in title block; DocumentNumber: 4; Revision: Use project parameter SCH_Rev; SheetNumber: 4; SheetTotal: 5; PageSetup: Record=PageOptions¦CenterHorizontal=True¦CenterVertical=True¦PrintScale=1.00¦XCorrection=1.00¦YCorrection=1.00¦PrintKind=0¦BorderSize=5000000¦LeftOffset=0¦BottomOffset=0¦Orientation=2¦PaperLength=1000¦PaperWidth=1000¦Scale=100¦PaperSource=15¦PrintQuality=600¦MediaType=1¦DitherType=10¦PaperKind=Letter¦PrintScaleMode=1
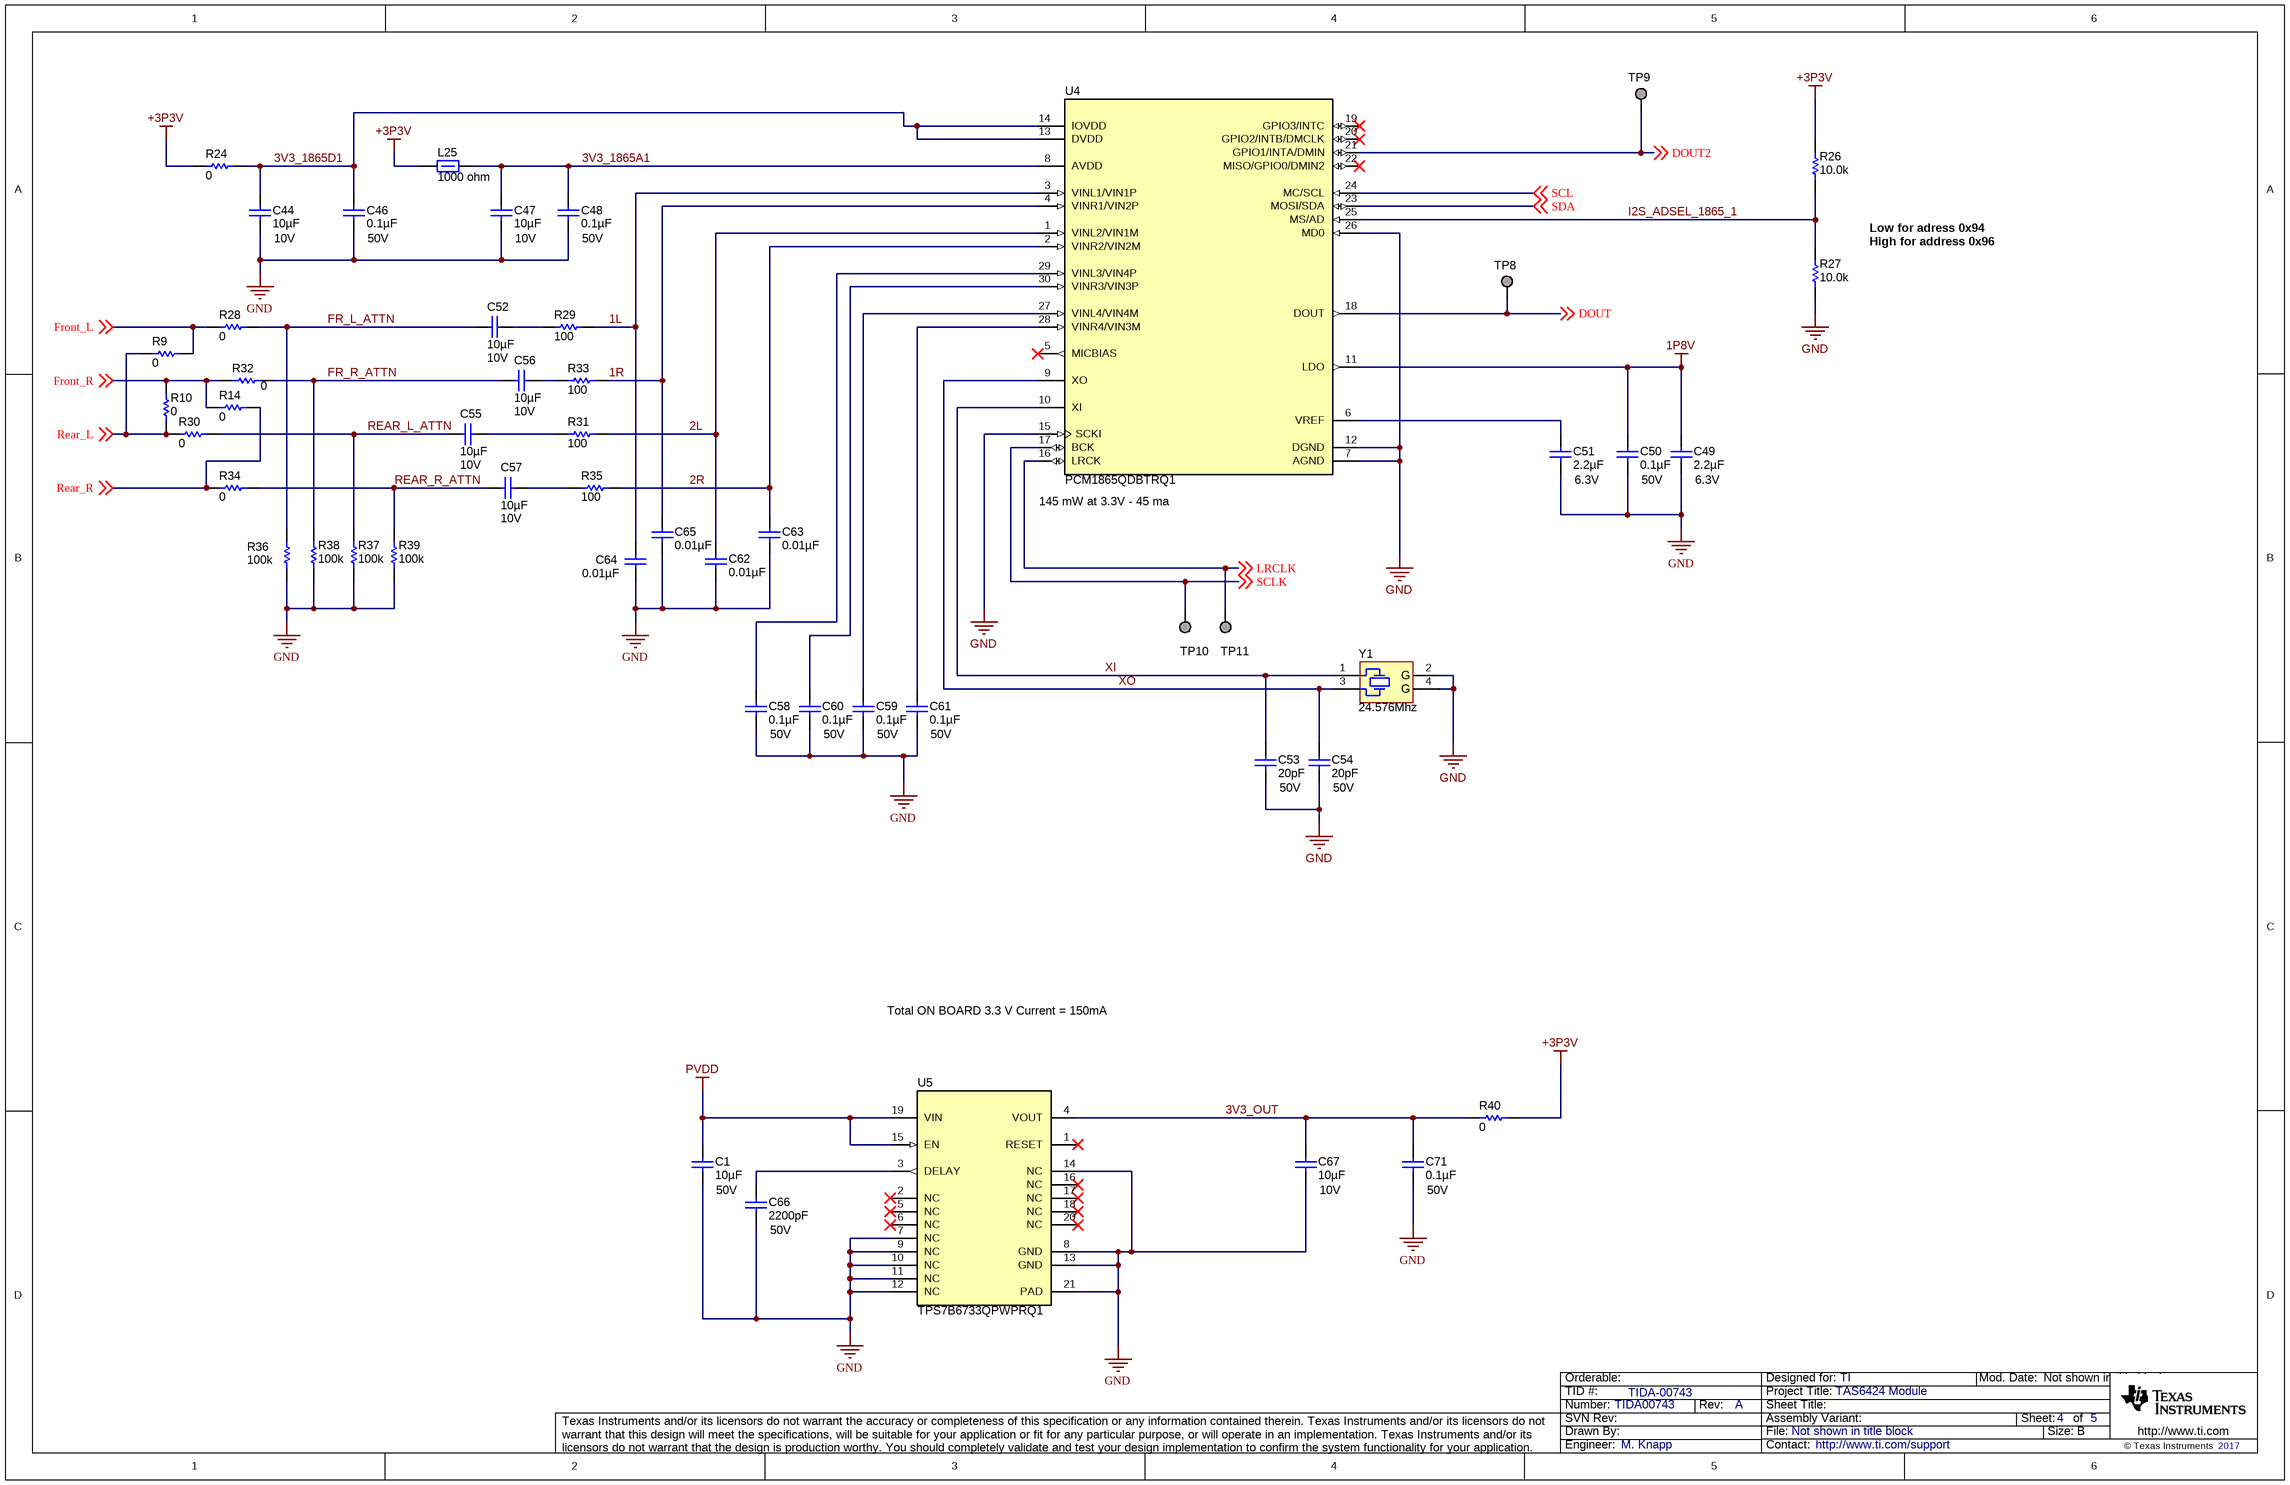
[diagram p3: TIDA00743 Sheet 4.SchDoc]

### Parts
C1  ValueDisplayed: 10µF  Value2: 50V  [1210L]  (hidden comment: GRM32ER71H106KA12L)
C44  ValueDisplayed: 10µF  Value2: 10V  [0805L]  (hidden comment: GRM21BR71A106KE51L)
C46  ValueDisplayed: 0.1µF  Value2: 50V  [0402L]  (hidden comment: C1005X7R1H104K050BB)
C47  ValueDisplayed: 10µF  Value2: 10V  [0805L]  (hidden comment: GRM21BR71A106KE51L)
C48  ValueDisplayed: 0.1µF  Value2: 50V  [0402L]  (hidden comment: C1005X7R1H104K050BB)
C49  ValueDisplayed: 2.2µF  Value2: 6.3V  [0603L]  (hidden comment: GCM188R70J225KE22D)
C50  ValueDisplayed: 0.1µF  Value2: 50V  [0402L]  (hidden comment: C1005X7R1H104K050BB)
C51  ValueDisplayed: 2.2µF  Value2: 6.3V  [0603L]  (hidden comment: GCM188R70J225KE22D)
C52  ValueDisplayed: 10µF  Value2: 10V  [0805L]  (hidden comment: GRM21BR71A106KE51L)
C53  ValueDisplayed: 20pF  Value2: 50V  [0402L]  (hidden comment: GRM1555C1H200JA01D)
C54  ValueDisplayed: 20pF  Value2: 50V  [0402L]  (hidden comment: GRM1555C1H200JA01D)
C55  ValueDisplayed: 10µF  Value2: 10V  [0805L]  (hidden comment: GRM21BR71A106KE51L)
C56  ValueDisplayed: 10µF  Value2: 10V  [0805L]  (hidden comment: GRM21BR71A106KE51L)
C57  ValueDisplayed: 10µF  Value2: 10V  [0805L]  (hidden comment: GRM21BR71A106KE51L)
C58  ValueDisplayed: 0.1µF  Value2: 50V  [0402L]  (hidden comment: C1005X7R1H104K050BB)
C59  ValueDisplayed: 0.1µF  Value2: 50V  [0402L]  (hidden comment: C1005X7R1H104K050BB)
C60  ValueDisplayed: 0.1µF  Value2: 50V  [0402L]  (hidden comment: C1005X7R1H104K050BB)
C61  ValueDisplayed: 0.1µF  Value2: 50V  [0402L]  (hidden comment: C1005X7R1H104K050BB)
C62  ValueDisplayed: 0.01µF  [0402L]  (hidden comment: GCM155R71H103KA55D)
C63  ValueDisplayed: 0.01µF  [0402L]  (hidden comment: GCM155R71H103KA55D)
C64  ValueDisplayed: 0.01µF  [0402L]  (hidden comment: GCM155R71H103KA55D)
C65  ValueDisplayed: 0.01µF  [0402L]  (hidden comment: GCM155R71H103KA55D)
C66  ValueDisplayed: 2200pF  Value2: 50V  [0402L]  (hidden comment: C1005X7R1H222K)
C67  ValueDisplayed: 10µF  Value2: 10V  [0805L]  (hidden comment: GRM21BR71A106KE51L)
C71  ValueDisplayed: 0.1µF  Value2: 50V  [0402L]  (hidden comment: C1005X7R1H104K050BB)
L25  ValueDisplayed: 1000 ohm  [0402L]  (hidden comment: BLM15HG102SN1D)
R9  ValueDisplayed: 0  [0402L]  (hidden comment: CRCW04020000Z0ED)
R10  ValueDisplayed: 0  [0402L]  (hidden comment: CRCW04020000Z0ED)
R14  ValueDisplayed: 0  [0402L]  (hidden comment: CRCW04020000Z0ED)
R24  ValueDisplayed: 0  [0402L]  (hidden comment: CRCW04020000Z0ED)
R26  ValueDisplayed: 10.0k  [0402L]  (hidden comment: CRCW040210K0FKED)
R27  ValueDisplayed: 10.0k  [0402L]  (hidden comment: CRCW040210K0FKED)
R28  ValueDisplayed: 0  [0402L]  (hidden comment: CRCW04020000Z0ED)
R29  ValueDisplayed: 100  [0402L]  (hidden comment: CRCW0402100RFKED)
R30  ValueDisplayed: 0  [0402L]  (hidden comment: CRCW04020000Z0ED)
R31  ValueDisplayed: 100  [0402L]  (hidden comment: CRCW0402100RFKED)
R32  ValueDisplayed: 0  [0402L]  (hidden comment: CRCW04020000Z0ED)
R33  ValueDisplayed: 100  [0402L]  (hidden comment: CRCW0402100RFKED)
R34  ValueDisplayed: 0  [0402L]  (hidden comment: CRCW04020000Z0ED)
R35  ValueDisplayed: 100  [0402L]  (hidden comment: CRCW0402100RFKED)
R36  ValueDisplayed: 100k  [0402L]  (hidden comment: CRCW0402100KFKED)
R37  ValueDisplayed: 100k  [0402L]  (hidden comment: CRCW0402100KFKED)
R38  ValueDisplayed: 100k  [0402L]  (hidden comment: CRCW0402100KFKED)
R39  ValueDisplayed: 100k  [0402L]  (hidden comment: CRCW0402100KFKED)
R40  ValueDisplayed: 0  [0402L]  (hidden comment: CRCW04020000Z0ED)
TP8  TESTPOINT  [PAD_1MM_SQUARE]  (value not drawn)  (no BOM)
TP9  TESTPOINT  [PAD_1MM_SQUARE]  (value not drawn)  (no BOM)
TP10  TESTPOINT  [PAD_1MM_SQUARE]  (value not drawn)  (no BOM)
TP11  TESTPOINT  [PAD_1MM_SQUARE]  (value not drawn)  (no BOM)
U4  PCM1865QDBTRQ1  [DBT0030A_N]
U5  TPS7B6733QPWPRQ1  [PWP0020D_N]
Y1  Frequency: 24.576Mhz  [XTAL_ABM10]  (hidden comment: ABM10-24.576MHZ-E20-T)

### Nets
1P8V: C49.1 C50.1 U4.11(LDO)
+3P3V: L25.2 R24.2 R26.2 R40.1
GND: C1.2 C44.2 C46.2 C47.2 C48.2 C49.2 C50.2 C51.2 C53.2 C54.2 C58.2 C59.2 C60.2 C61.2 C62.2 C63.2 C64.2 C65.2 C66.2 C67.2 C71.2 R27.1 R36.1 R37.1 R38.1 R39.1 U4.7(AGND) U4.12(DGND) U4.15(SCKI) U4.26(MD0) U5.7(NC) U5.8(GND) U5.9(NC) U5.10(NC) U5.11(NC) U5.12(NC) U5.13(GND) U5.14(NC) U5.21(PAD) Y1.2(GND) Y1.4(GND)
PVDD: C1.1 U5.15(EN) U5.19(VIN)
1L: C64.1 R29.2 U4.3(VINL1/VIN1P)
1R: C65.1 R33.2 U4.4(VINR1/VIN2P)
2L: C62.1 R31.2 U4.1(VINL2/VIN1M)
2R: C63.1 R35.2 U4.2(VINR2/VIN2M)
3V3_1865A1: C47.1 C48.1 L25.1 U4.8(AVDD)
3V3_1865D1: C44.1 C46.1 R24.1 U4.13(DVDD) U4.14(IOVDD)
3V3_OUT: C67.1 C71.1 R40.2 U5.4(VOUT)
DOUT: TP8.1 U4.18(DOUT) ; off-sheet DOUT
DOUT2: TP9.1 U4.21(GPIO1/INTA/DMIN) ; off-sheet DOUT2
FR_L_ATTN: C52.1 R28.1 R36.2
FR_R_ATTN: C56.1 R32.1 R38.2
Front_L: R9.1 R28.2 ; off-sheet Front_L
Front_R: R10.1 R14.2 R32.2 ; off-sheet Front_R
I2S_ADSEL_1865_1: R26.1 R27.2 U4.25(MS/AD)
LRCLK: TP11.1 U4.16(LRCK) ; off-sheet LRCLK
Rear_L: R9.2 R10.2 R30.2 ; off-sheet Rear_L
REAR_L_ATTN: C55.1 R30.1 R37.2
Rear_R: R14.1 R34.2 ; off-sheet Rear_R
REAR_R_ATTN: C57.1 R34.1 R39.2
SCL: U4.24(MC/SCL) ; off-sheet SCL
SCLK: TP10.1 U4.17(BCK) ; off-sheet SCLK
SDA: U4.23(MOSI/SDA) ; off-sheet SDA
XI: C53.1 U4.10(XI) Y1.1
XO: C54.1 U4.9(XO) Y1.3
NetC51_1: C51.1 U4.6(VREF)
NetC52_2: C52.2 R29.1
NetC55_2: C55.2 R31.1
NetC56_2: C56.2 R33.1
NetC57_2: C57.2 R35.1
NetC58_1: C58.1 U4.29(VINL3/VIN4P)
NetC59_1: C59.1 U4.27(VINL4/VIN4M)
NetC60_1: C60.1 U4.30(VINR3/VIN3P)
NetC61_1: C61.1 U4.28(VINR4/VIN3M)
NetC66_1: C66.1 U5.3(DELAY)

Not connected (* = marked no-connect by the designer): U4 5(MICBIAS)* 19(GPIO3/INTC)* 20(GPIO2/INTB/DMCLK)* 22(MISO/GPIO0/DMIN2)*; U5 1(RESET)* 2(NC)* 5(NC)* 6(NC)* 16(NC)* 17(NC)* 18(NC)* 20(NC)*

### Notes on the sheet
- Low for adress 0x94
  High for address 0x96
- (near U4) 145 mW at 3.3V - 45 ma
- Total ON BOARD 3.3 V Current = 150mA

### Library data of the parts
C1 = GRM32ER71H106KA12L: as C2 on sheet TIDA00743 Sheet 2
C44 C47 C52 C55-C57 C67 = GRM21BR71A106KE51L: CAP, CERM, 10 µF, 10 V, +/- 10%, X7R, 0805; Manufacturer: MuRata; Polarized: N; CompType: Capacitor; Value: 10uF; U/M: EA; Cap_F: 0.00001; Tolerance_%: 10; ESR_ohm: 0.003; Value1: 0.003 ohm; TaMin_C: -55; TaMax_C: 125; Cap_Case: 0805; AEC Category: Q200
C46 C48 C50 C58-C61 C71 = C1005X7R1H104K050BB: as C3 on sheet TIDA00743 Sheet 2
C49 = GCM188R70J225KE22D: CAP, CERM, 2.2 µF, 6.3 V, +/- 10%, X7R, AEC-Q200 Grade 1, 0603; Manufacturer: MuRata; Polarized: N; CompType: Capacitor; Value: 2.2uF; U/M: EA; Cap_F: 0.0000022; Tolerance_%: 10; Value1: Unknown; VDC_V: 6.3; TaMin_C: -55; TaMax_C: 125; Cap_Case: 0603; AEC Category: Q200; AEC Qualified: Y; AEC Grade: 1; SizeArea_mm2: 1.28; SizeAreaWB_mm2: 4.68; SizeX_mm: 1.6; SizeY_mm: 0.8
C51 = GCM188R70J225KE22D: CAP, CERM, 2.2 µF, 6.3 V, +/- 10%, X7R, AEC-Q200 Grade 1, 0603; Manufacturer: MuRata; Polarized: N; CompType: Capacitor; Value: 2.2uF; U/M: EA; Cap_F: 0.0000022; Tolerance_%: 10; Value1: Unknown; VDC_V: 6.3; TaMin_C: -55; TaMax_C: 125; Cap_Case: 0603; AEC Category: Q200; AEC Qualified: Y; AEC Grade: 1
C53 C54 = GRM1555C1H200JA01D: CAP, CERM, 20 pF, 50 V, +/- 5%, C0G/NP0, 0402; Manufacturer: MuRata; Polarized: N; CompType: Capacitor; Value: 20pF; U/M: EA; Cap_F: 0.00000000002; Tolerance_%: 5; Value1: Unknown; VDC_V: 50; TaMin_C: -55; TaMax_C: 125; Cap_Case: 0402; AEC Category: Q200
C62-C65 = GCM155R71H103KA55D: CAP, CERM, 0.01 µF, 50 V, +/- 10%, C0G/NP0, 0402; Manufacturer: MuRata; Polarized: N; CompType: Capacitor; Value: 0.01uF; U/M: EA; Cap_F: 0.00000001; Tolerance_%: 10; Value1: Unknown; VDC_V: 50; Value2: 50V; TaMin_C: -55; TaMax_C: 125; Cap_Case: 0402; AEC Category: Q200; SizeArea_mm2: 0.5; SizeAreaWB_mm2: 3; SizeX_mm: 1; SizeZ_mm: 0.6
C66 = C1005X7R1H222K: as C43 on sheet TIDA00743 Sheet 3
L25 = BLM15HG102SN1D: Ferrite Bead, 1000 ohm @ 100 MHz, 0.25 A, 0402; Manufacturer: MuRata; Value1: 1.1 ohm; Value2: 0.25A; Imax_A: 0.25; DCR_ohm: 1.1; SizeAreaWB_mm2: 3; SizeArea_mm2: 0.5; SizeX_mm: 1; SizeZ_mm: 0.6; ZTyp@100MHz_Ohm: 1000
R9 R10 R14 R24 R28 R30 R32 R34 R40 = CRCW04020000Z0ED: as R3 on sheet TIDA00743 Sheet 2
R26 R27 = CRCW040210K0FKED: as R7 on sheet TIDA00743 Sheet 2
R29 R31 R33 R35 = CRCW0402100RFKED: RES, 100, 1%, 0.063 W, 0402; Manufacturer: Vishay-Dale; CompType: Resistor; Value: 100; Value_Code: 100R; Tolerance_%: 1; Power_W: 0.063; Value2: 0.063W; VDC_V: 50; TempCo: 100 ppm/C; EIA_Code: E96; U/M: EA; AEC Category: Q200
R36-R39 = CRCW0402100KFKED: as R5 on sheet TIDA00743 Sheet 2
TP8-TP11 = PAD_1MM_SQUARE: as TP1 on sheet TIDA00743 Sheet 3
U4 = PCM1865QDBTRQ1: 110 dB 4ch Audio ADCs With Universal Front End, DBT0030A; Manufacturer: Texas Instruments; SymbolCreator: Altium; CompType: IC; U/M: EA; SizeArea_mm2: 49.92; SizeAreaWB_mm2: 82.32; SizeX_mm: 6.4; SizeY_mm: 7.8; SizeZ_mm: 1.2
U5 = TPS7B6733QPWPRQ1: Automotive 450-mA High-Voltage Ultra-Low IQ Low-Dropout Regulator, PWP0020D (TSSOP-20); Manufacturer: Texas Instruments; SymbolCreator: Altium; CompType: IC; U/M: EA; SizeArea_mm2: 41.6; SizeAreaWB_mm2: 71.4; SizeX_mm: 6.4; SizeY_mm: 6.5; SizeZ_mm: 1.2
Y1 = ABM10-24.576MHZ-E20-T: Crystal, 24.576MHz, 10pF, SMD; Manufacturer: Abracon Corporation; SymbolCreator: a0412235; U/M: EA; TaMin_C: -20; TaMax_C: 70; Frequency Stability: ±20ppm

## Sheet TIDA00743 Sheet 5.SchDoc
size 431 x 279 mm; Date: Not shown in title block; ApprovedBy: Not shown in title block; CheckedBy: Not shown in title block; Author: Not shown in title block; CompanyName: Not shown in title block; Engineer: Not shown in title block; Organization: Not shown in title block; Address1: Not shown in title block; Address2: Not shown in title block; Address3: Not shown in title block; Address4: Not shown in title block; DocumentNumber: 5; Revision: Use project parameter SCH_Rev; SheetNumber: 5; SheetTotal: 5; PageSetup: Record=PageOptions¦CenterHorizontal=True¦CenterVertical=True¦PrintScale=1.00¦XCorrection=1.00¦YCorrection=1.00¦PrintKind=0¦BorderSize=5000000¦LeftOffset=0¦BottomOffset=0¦Orientation=2¦PaperLength=1000¦PaperWidth=1000¦Scale=100¦PaperSource=15¦PrintQuality=600¦MediaType=1¦DitherType=10¦PaperKind=Letter¦PrintScaleMode=1
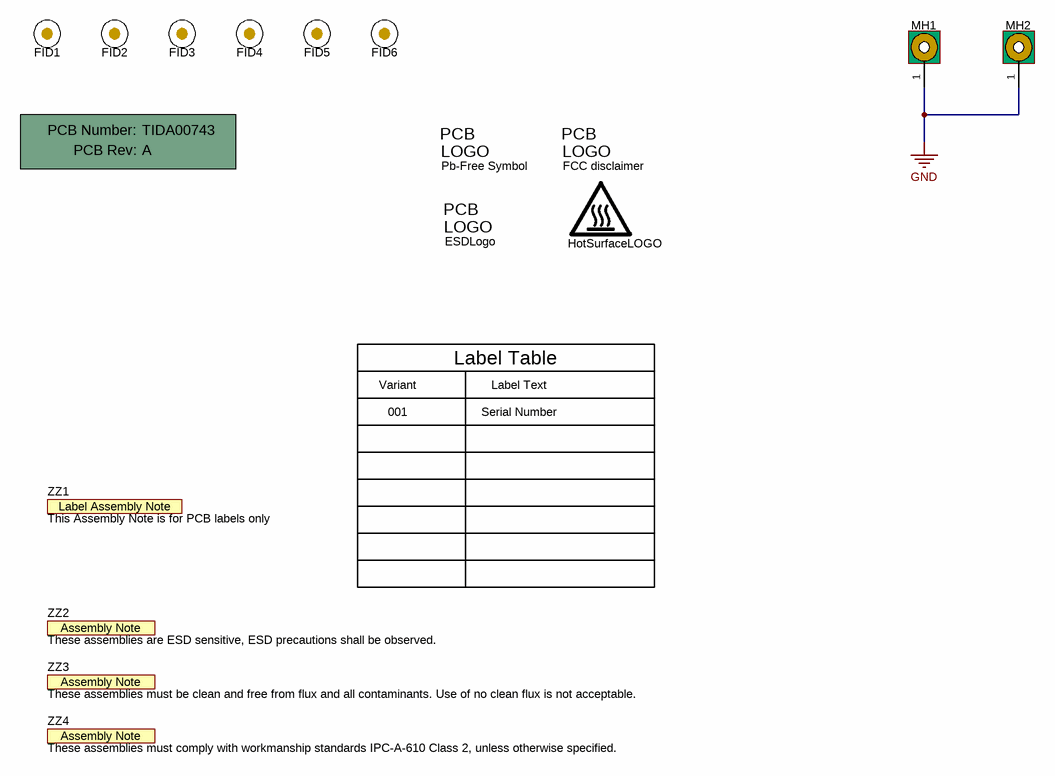
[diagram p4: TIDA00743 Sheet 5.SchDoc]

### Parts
!PCB1  Printed Circuit Board  (value not drawn)  (mechanical)
ESDLogo  ESD Susceptible  [ESD_Overlay_Small]  (value not drawn)  (no BOM)
FID1  Fiducial  [Fiducial10-20]  (value not drawn)
FID2  Fiducial  [Fiducial10-20]  (value not drawn)
FID3  Fiducial  [Fiducial10-20]  (value not drawn)
FID4  Fiducial  [Fiducial10-20]  (value not drawn)
FID5  Fiducial  [Fiducial10-20]  (value not drawn)
FID6  Fiducial  [Fiducial10-20]  (value not drawn)
HotSurfaceLOGO  CAUTION HOT SURFACE  [IEC_HotSurface_Small]  (value not drawn)  (no BOM)
Logo2  Pb-Free Symbol  [Pb-Free_Overlay_Small]  (no BOM)
Logo3  FCC disclaimer  [FCC_disclaimer_stacked]  (no BOM)
MH1  MTG_Pads  [MTGP_2-48_PanHead]  (value not drawn)  (no BOM)
MH2  MTG_Pads  [MTGP_2-48_PanHead]  (value not drawn)  (no BOM)
ZZ1  This Assembly Note is for PCB labels only  [AssemblyNoteLabel]  (no BOM)
ZZ2  These assemblies are ESD sensitive, ESD precautions shall be observed.  [AssemblyNote]  (no BOM)
ZZ3  These assemblies must be clean and free from flux and all contaminants. Use of no clean flux is not acceptable.  [AssemblyNote]  (no BOM)
ZZ4  These assemblies must comply with workmanship standards IPC-A-610 Class 2, unless otherwise specified.  [AssemblyNote]  (no BOM)

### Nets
GND: MH1.1 MH2.1

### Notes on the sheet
- Variant
- Label Table
- Label Text
- 001
- Serial Number

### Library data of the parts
!PCB1 = PCB: Manufacturer: Any; PartNumber: TIDA00743; SymbolCreator: a0412235
ESDLogo = ESD_Susceptible: ESD Susceptible Symbol; SymbolCreator: a0412235
FID1-FID6 = Fiducial: Fiducial mark.  There is nothing to buy or mount.; SymbolCreator: codlsc
HotSurfaceLOGO = IEC_HotSurface: IEC 61010-1 Hot Surface Warning; SymbolCreator: a0412235
Logo2 = Pb-Free: SymbolCreator: a0412235
Logo3 = FCC_disclaimer: SymbolCreator: codlsc
MH1 MH2 = Mounting Hole (Imperial) with Pads: PCB Mounting Hole; Manufacturer: Any; SymbolCreator: a0412235
ZZ1 = AssemblyNoteLabel: SymbolCreator: a0412235
ZZ2-ZZ4 = AssemblyNote: SymbolCreator: codlsc

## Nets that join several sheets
+3P3V: TIDA00743 Sheet 2 (7 pins), TIDA00743 Sheet 3 (10 pins), TIDA00743 Sheet 4 (L25.2 R24.2 R26.2 R40.1)
GND: TIDA00743 Sheet 2 (40 pins), TIDA00743 Sheet 3 (15 pins), TIDA00743 Sheet 4 (41 pins), TIDA00743 Sheet 5 (MH1.1 MH2.1)
PVDD: TIDA00743 Sheet 2 (16 pins), TIDA00743 Sheet 3 (J6.7 J6.8), TIDA00743 Sheet 4 (C1.1 U5.15 U5.19)
DOUT: TIDA00743 Sheet 2 (U1.15), TIDA00743 Sheet 4 (TP8.1 U4.18)
DOUT2: TIDA00743 Sheet 2 (U1.16), TIDA00743 Sheet 4 (TP9.1 U4.21)
Front_L: TIDA00743 Sheet 3 (J6.1), TIDA00743 Sheet 4 (R9.1 R28.2)
Front_R: TIDA00743 Sheet 3 (J6.3), TIDA00743 Sheet 4 (R10.1 R14.2 R32.2)
LRCLK: TIDA00743 Sheet 2 (U1.14), TIDA00743 Sheet 4 (TP11.1 U4.16)
MCLK: TIDA00743 Sheet 2 (U1.12), TIDA00743 Sheet 3 (TP1.1 U2.6)
nFAULT1: TIDA00743 Sheet 2 (D1.1 U1.26), TIDA00743 Sheet 3 (J6.34 U3.8)
nMUTE: TIDA00743 Sheet 2 (R7.1 U1.25), TIDA00743 Sheet 3 (J6.30)
nSTANDBY: TIDA00743 Sheet 2 (R8.1 U1.24), TIDA00743 Sheet 3 (J6.29 U3.11)
nWARN1: TIDA00743 Sheet 2 (D2.1 U1.27), TIDA00743 Sheet 3 (J6.33 U3.9)
OUT1+: TIDA00743 Sheet 2 (C37.1 C38.1 L7.2), TIDA00743 Sheet 3 (J6.25 J6.26)
OUT1-: TIDA00743 Sheet 2 (C39.1 C40.1 L8.2), TIDA00743 Sheet 3 (J6.27 J6.28)
OUT2+: TIDA00743 Sheet 2 (C31.1 C32.1 L5.2), TIDA00743 Sheet 3 (J6.21 J6.22)
OUT2-: TIDA00743 Sheet 2 (C35.1 C36.1 L6.2), TIDA00743 Sheet 3 (J6.23 J6.24)
OUT3+: TIDA00743 Sheet 2 (C17.1 C18.1 L3.2), TIDA00743 Sheet 3 (J6.15 J6.16)
OUT3-: TIDA00743 Sheet 2 (C25.1 C26.1 L4.2), TIDA00743 Sheet 3 (J6.17 J6.18)
OUT4+: TIDA00743 Sheet 2 (C10.1 C11.1 L1.2), TIDA00743 Sheet 3 (J6.11 J6.12)
OUT4-: TIDA00743 Sheet 2 (C12.1 C13.1 L2.2), TIDA00743 Sheet 3 (J6.13 J6.14)
Rear_L: TIDA00743 Sheet 3 (J6.2), TIDA00743 Sheet 4 (R9.2 R10.2 R30.2)
Rear_R: TIDA00743 Sheet 3 (J6.4), TIDA00743 Sheet 4 (R14.1 R34.2)
SCL: TIDA00743 Sheet 2 (U1.20), TIDA00743 Sheet 3 (R16.1 R22.2 TP3.1 U3.14), TIDA00743 Sheet 4 (U4.24)
SCLK: TIDA00743 Sheet 2 (U1.13), TIDA00743 Sheet 3 (U2.1), TIDA00743 Sheet 4 (TP10.1 U4.17)
SDA: TIDA00743 Sheet 2 (U1.21), TIDA00743 Sheet 3 (R17.1 R20.2 TP2.1 U3.15), TIDA00743 Sheet 4 (U4.23)

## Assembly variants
001: not fitted FID1 FID2 FID3 R5 R9 R10 R14 R18 R20 R22 R26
